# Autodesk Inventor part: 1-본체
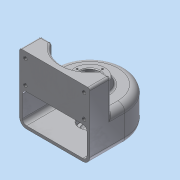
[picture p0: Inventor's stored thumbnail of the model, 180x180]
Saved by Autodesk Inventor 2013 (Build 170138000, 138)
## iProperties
Created: 2015-02
Part Number: 1-본체
Material: 알루미늄 6061
Document SubType Name: Modeling
Designer: Administrator
Density: 2.40731 g/cm^3
Mass: 511.244 g
Surface Area: 706.56 cm^2
Volume: 212.371 cm^3
Author: Administrator
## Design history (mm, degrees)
sketch "스케치1" dims "d0" = 50
  geometry: L1 (50, 0)-(-50, 0); L2 (-50, 0)-(-50, -50); L3 (-50, -50)-(50, -50); L4 (50, -50)-(50, 0); 2 further points
  constraints: 8 end point, 2 parallel, 2 vertical, 1 coincident, 1 horizontal, 1 horizontal alignment, 1 perpendicular, 2 other
  dimensions: "d2" = 50 distance between parallel lines of L3 L1
extrude "돌출1" new body sketch "스케치1" distance "d3" = 50; taper "d4" = 0 deg
fillet "모깎기1" dims "d5" = 10
node "작업 평면1"
feature "쉘1" dims "d28" = 4
sketch "스케치2"
  geometry: L1 (-40, -50)-(40, -50) reference; L2 (-40, -50)-(-50, -50) reference; L3 (50, -50)-(40, -50) reference; L4 (50, -50)-(50, 0) reference; L5 (-50, 0)-(-50, -50) reference; L6 (-50, -20)-(-34.641, -20); L7 (-34.641, -20)-(34.641, -20); L8 (34.641, -20)-(50, -20); A1 r 40 centre (0, 0) between (-34.641, -20) and (34.641, -20); A2 r 40 centre (0, 0) between (34.641, -20) and (-34.641, -20); 1 further point
  constraints: 6 end point, 4 point on circle, 3 perpendicular, 2 centre point, 2 point on line, 1 coincident
  dimensions: "d7" = 40 radius of A1; "d9" = 30 distance between parallel lines of L1 L6
extrude "돌출2" join sketch "스케치2" stored distance "d10" = 50; taper "d11" = 0 deg
sketch "스케치3"
  geometry: C1 r 25 at (0, 0); A1 r 40 centre (0, 0) between (-34.641, -20) and (34.641, -20) reference
  constraints: 1 centre point, 1 coincident
  dimensions: "d12" = 50 diameter of C1
extrude "돌출3" join sketch "스케치3" distance "d14" = 10; taper "d15" = -20 deg
sketch "스케치4"
  geometry: C1 r 20 at (0, 1.303); A1 r 40 centre (0, 1.303) between (40, 1.303) and (-40, 1.303) reference
  constraints: 1 centre point, 1 coincident
  dimensions: "d16" = 40 diameter of C1
extrude "돌출4" join sketch "스케치4" taper "d18" = 0 deg; distance "d19" = 9
sketch "스케치5"
  geometry: C1 r 21.36 at (0, 0) reference; 1 further point
  constraints: 1 coincident
hole "구멍1" sketch "스케치5" at (0, 0) diameter "d21" = 20; stored, may be unused: countersink angle "d25" = 90 deg, drill point angle "d27" = 0 deg; dims "d22" = 6, "d23" = 28, "d24" = 10, "d26" = 14
sketch "스케치6"
  geometry: C1 r 21.36 at (0, 8.803); A1 r 40 centre (0, 8.803) between (40, 8.803) and (-40, 8.803) reference; 1 further point
  constraints: 2 coincident, 1 centre point
hole "구멍2" sketch "스케치6" at (0, 8.803) diameter "d35" = 20; stored, may be unused: drill point angle "d30" = 0 deg, countersink angle "d31" = 90 deg; dims "d29" = 6, "d32" = 8, "d33" = 28, "d34" = 10
chamfer "모따기1" distance "d36" = 1; stored, may be unused: second distance "d37" = 2, angle "d38" = 45 deg
fillet "모깎기2" dims "d39" = 0.3, "d40" = 3
sketch "스케치7"
  geometry: C1 r 21.36 at (0, 0) reference; 4 further points
  constraints: 1 vertical alignment, 5 other
  dimensions: "d43" = 360 deg dimension on C1.centre point (0, 18) (derived); "d45" = 36 distance of point (0, -18) point (0, 18)
hole "구멍3" sketch "스케치7" at (0, 18), (-18, 0), (0, -18), (18, 0) diameter "d46" = 2.459; stored, may be unused: countersink angle "d50" = 90 deg, drill point angle "d52" = 118 deg; dims "d47" = 6, "d48" = 28, "d49" = 10, "d51" = 9
sketch "스케치8"
  geometry: L1 (-7, 95)-(87, 95) reference; L2 (81.75, 86)-(-1.75, 86); L3 (-1.75, 86)-(-1.75, 53); L4 (-1.75, 53)-(81.75, 53); L5 (81.75, 53)-(81.75, 86); 7 further points
  constraints: 8 end point, 4 coincident, 2 midpoint, 2 parallel, 1 horizontal, 1 perpendicular, 1 vertical alignment
  dimensions: "d53" = 33 distance of L4.end L2.start; "d55" = 83.5 distance of L2.start L2.end; "d56" = 9 distance between parallel lines of L1 L2
hole "구멍4" sketch "스케치8" at (81.75, 86), (81.75, 53), (-1.75, 86), (-1.75, 53) diameter "d57" = 5.134; stored, may be unused: countersink angle "d61" = 90 deg, drill point angle "d63" = 118 deg; dims "d58" = 10, "d59" = 28, "d60" = 10, "d62" = 13
node "작업 평면2"
sketch "스케치9"
  geometry: L1 (40, 0)-(-40, 0) reference; 2 further points
  constraints: 1 vertical alignment, 1 other
  dimensions: "d65" = 25 distance from line of L1 point (0, 25)
feature "엠보싱1" sketch "스케치9" dims "d0" = 50, "d2" = 50, "d9" = 30, "d66" = 0.5, "d67" = 0
node "솔리드1"
other parameters: "d6" = -95, "d64" = 76
